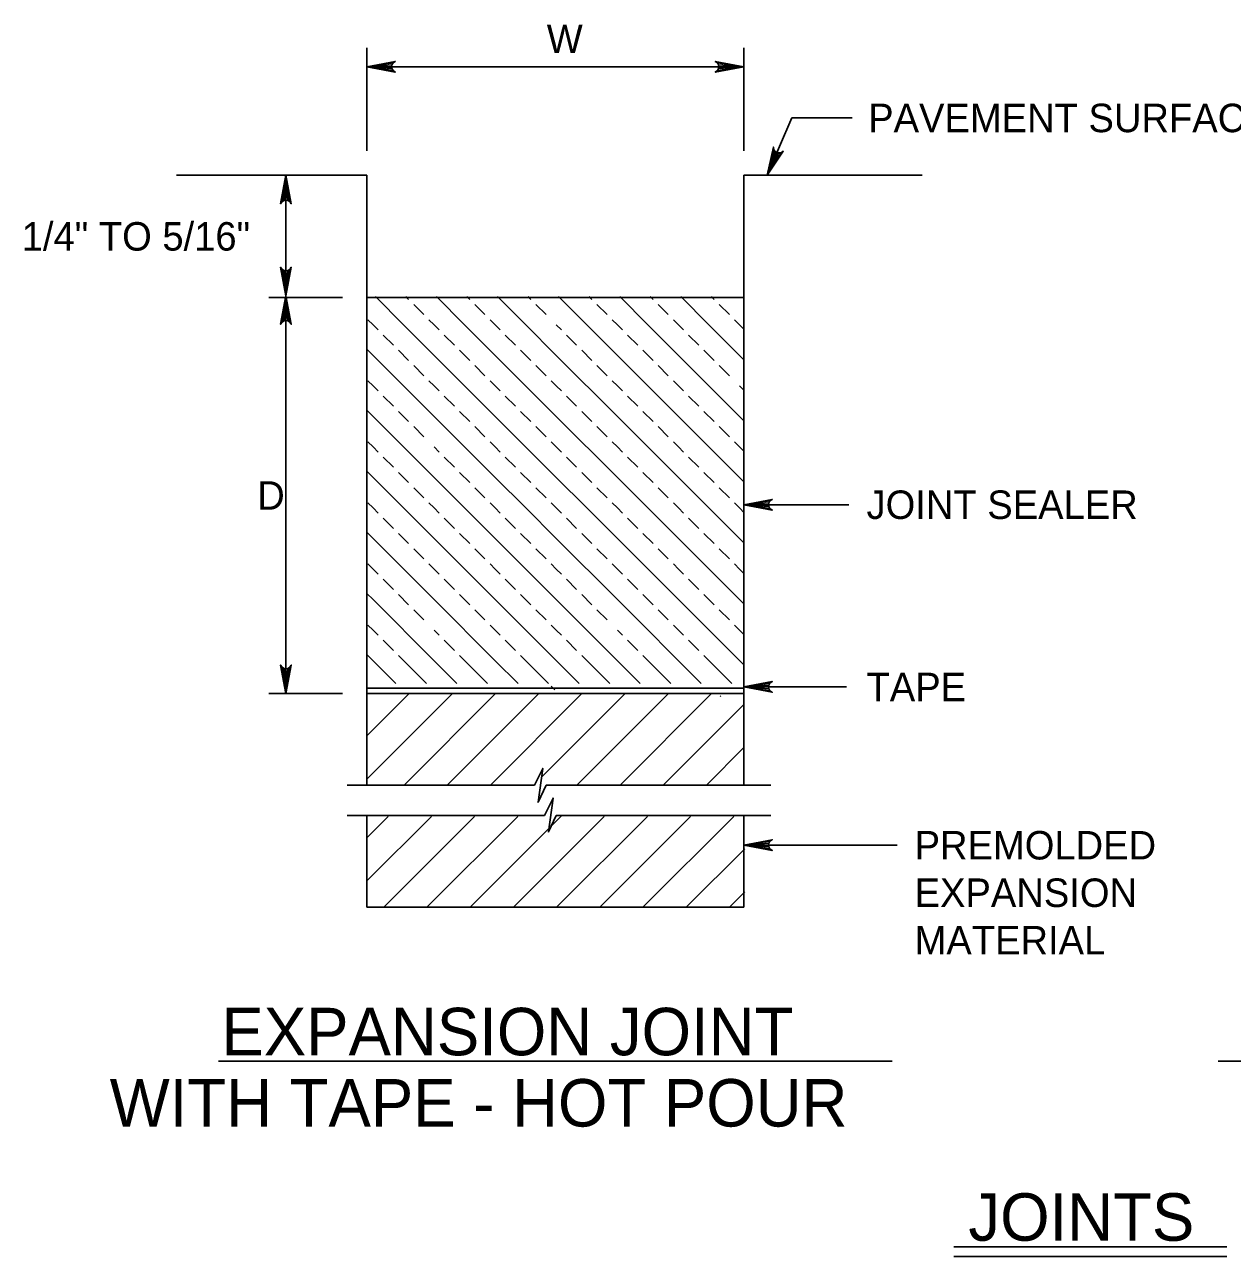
# Model space of a CAD drawing. Extents: x 1.68 to 8.95, y -3.21 to 6.76.
# Drawn here: x 3.018 to 5.56, y 4.163 to 6.756 of the extents above; entities that cross this region are included whole.
import ezdxf

# ---------------------------------------------------------------- set-up
doc = ezdxf.new("R2010")
doc.units = 0
for name, color, linetype in [('DETL-DIMS', 7, 'Continuous'), ('DETL-LINE', 7, 'Continuous'), ('DETL-NOTE', 7, 'Continuous'), ('DETL-PATT', 7, 'Continuous'), ('DETL-TITL', 7, 'Continuous')]:
    doc.layers.add(name, color=color, linetype=linetype)

msp = doc.modelspace()

# ---------------------------------------------------------------- linework, layer by layer
at = {"layer": 'DETL-DIMS'}
for p, q in [((3.7384, 6.7077), (3.7384, 6.4907)), ((4.5316, 6.7077), (4.5316, 6.4907)), ((3.7384, 6.6679), (4.5316, 6.6679)), ((4.5807, 6.4393), (4.633, 6.56)), ((4.7598, 6.56), (4.633, 6.56)), ((3.5682, 6.1821), (3.5682, 6.4393)), ((3.5323, 6.1821), (3.6869, 6.1821)), ((3.5682, 6.1821), (3.5682, 5.3482)), ((4.5316, 5.7457), (4.7529, 5.7457)), ((3.5323, 5.3482), (3.6869, 5.3482)), ((4.5316, 5.362), (4.7483, 5.362)), ((4.5316, 5.0292), (4.8547, 5.0292))]:
    msp.add_line(p, q, dxfattribs=at)
for points in [[(3.7384, 6.6679), (3.7983, 6.6791), (3.7937, 6.6759), (3.7913, 6.6719), (3.7906, 6.6679), (3.7913, 6.6639), (3.7937, 6.6598), (3.7983, 6.6566), (3.7384, 6.6679), (3.7937, 6.6598), (3.7913, 6.6639), (3.7384, 6.6679), (3.7906, 6.6679), (3.7913, 6.6719), (3.7384, 6.6679), (3.7937, 6.6759)], [(3.7384, 6.6679), (3.7983, 6.6791), (3.7937, 6.6759), (3.7913, 6.6719), (3.7906, 6.6679), (3.7913, 6.6639), (3.7937, 6.6598), (3.7983, 6.6566), (3.7384, 6.6679), (3.7937, 6.6598), (3.7913, 6.6639), (3.7384, 6.6679), (3.7906, 6.6679), (3.7913, 6.6719), (3.7384, 6.6679), (3.7937, 6.6759)], [(4.5316, 6.6679), (4.4717, 6.6566), (4.4763, 6.6598), (4.4787, 6.6639), (4.4794, 6.6679), (4.4787, 6.6719), (4.4763, 6.6759), (4.4717, 6.6791), (4.5316, 6.6679), (4.4763, 6.6759), (4.4787, 6.6719), (4.5316, 6.6679), (4.4794, 6.6679), (4.4787, 6.6639), (4.5316, 6.6679), (4.4763, 6.6598)], [(4.5807, 6.4393), (4.5942, 6.4987), (4.5953, 6.4932), (4.5981, 6.4894), (4.6015, 6.4872), (4.6055, 6.4862), (4.6101, 6.4868), (4.6149, 6.4898), (4.5807, 6.4393), (4.6101, 6.4868), (4.6055, 6.4862), (4.5807, 6.4393), (4.6015, 6.4872), (4.5981, 6.4894), (4.5807, 6.4393), (4.5953, 6.4932)], [(3.5682, 6.4393), (3.5794, 6.3794), (3.5762, 6.384), (3.5722, 6.3864), (3.5682, 6.387), (3.5641, 6.3864), (3.5601, 6.384), (3.5569, 6.3794), (3.5682, 6.4393), (3.5601, 6.384), (3.5641, 6.3864), (3.5682, 6.4393), (3.5682, 6.387), (3.5722, 6.3864), (3.5682, 6.4393), (3.5762, 6.384)], [(3.5682, 6.4393), (3.5794, 6.3794), (3.5762, 6.384), (3.5722, 6.3864), (3.5682, 6.387), (3.5641, 6.3864), (3.5601, 6.384), (3.5569, 6.3794), (3.5682, 6.4393), (3.5601, 6.384), (3.5641, 6.3864), (3.5682, 6.4393), (3.5682, 6.387), (3.5722, 6.3864), (3.5682, 6.4393), (3.5762, 6.384)], [(3.5682, 6.1856), (3.5794, 6.2456), (3.5762, 6.2409), (3.5722, 6.2386), (3.5682, 6.2379), (3.5641, 6.2386), (3.5601, 6.2409), (3.5569, 6.2456), (3.5682, 6.1856), (3.5601, 6.2409), (3.5641, 6.2386), (3.5682, 6.1856), (3.5682, 6.2379), (3.5722, 6.2386), (3.5682, 6.1856), (3.5762, 6.2409)], [(3.5682, 6.1856), (3.5794, 6.1257), (3.5762, 6.1303), (3.5722, 6.1327), (3.5682, 6.1334), (3.5641, 6.1327), (3.5601, 6.1303), (3.5569, 6.1257), (3.5682, 6.1856), (3.5601, 6.1303), (3.5641, 6.1327), (3.5682, 6.1856), (3.5682, 6.1334), (3.5722, 6.1327), (3.5682, 6.1856), (3.5762, 6.1303)], [(4.5316, 5.7457), (4.5916, 5.7569), (4.5869, 5.7537), (4.5846, 5.7497), (4.5839, 5.7457), (4.5846, 5.7417), (4.5869, 5.7376), (4.5916, 5.7344), (4.5316, 5.7457), (4.5869, 5.7376), (4.5846, 5.7417), (4.5316, 5.7457), (4.5839, 5.7457), (4.5846, 5.7497), (4.5316, 5.7457), (4.5869, 5.7537)], [(4.5316, 5.7457), (4.5916, 5.7569), (4.5869, 5.7537), (4.5846, 5.7497), (4.5839, 5.7457), (4.5846, 5.7417), (4.5869, 5.7376), (4.5916, 5.7344), (4.5316, 5.7457), (4.5869, 5.7376), (4.5846, 5.7417), (4.5316, 5.7457), (4.5839, 5.7457), (4.5846, 5.7497), (4.5316, 5.7457), (4.5869, 5.7537)], [(3.5682, 5.3482), (3.5569, 5.4082), (3.5601, 5.4035), (3.5641, 5.4012), (3.5682, 5.4005), (3.5722, 5.4012), (3.5762, 5.4035), (3.5794, 5.4082), (3.5682, 5.3482), (3.5762, 5.4035), (3.5722, 5.4012), (3.5682, 5.3482), (3.5682, 5.4005), (3.5641, 5.4012), (3.5682, 5.3482), (3.5601, 5.4035)], [(4.5316, 5.362), (4.5916, 5.3732), (4.5869, 5.37), (4.5846, 5.366), (4.5839, 5.362), (4.5846, 5.358), (4.5869, 5.354), (4.5916, 5.3508), (4.5316, 5.362), (4.5869, 5.354), (4.5846, 5.358), (4.5316, 5.362), (4.5839, 5.362), (4.5846, 5.366), (4.5316, 5.362), (4.5869, 5.37)], [(4.5316, 5.0292), (4.5916, 5.0404), (4.5869, 5.0372), (4.5846, 5.0332), (4.5839, 5.0292), (4.5846, 5.0252), (4.5869, 5.0212), (4.5916, 5.018), (4.5316, 5.0292), (4.5869, 5.0212), (4.5846, 5.0252), (4.5316, 5.0292), (4.5839, 5.0292), (4.5846, 5.0332), (4.5316, 5.0292), (4.5869, 5.0372)]]:
    msp.add_lwpolyline(points, dxfattribs=at)
at = {"layer": 'DETL-LINE'}
for p, q in [((3.3381, 6.4393), (3.7384, 6.4393)), ((3.7384, 5.1554), (3.7384, 6.4393)), ((4.5316, 6.4393), (4.5316, 5.1554)), ((4.5316, 6.4393), (4.9069, 6.4393)), ((3.7384, 6.1821), (4.5316, 6.1821)), ((3.8264, 6.178), (3.8207, 6.1838)), ((3.9549, 6.178), (3.9492, 6.1838)), ((4.0835, 6.178), (4.0778, 6.1838)), ((4.2121, 6.178), (4.2064, 6.1838)), ((4.3407, 6.178), (4.3349, 6.1838)), ((4.4692, 6.178), (4.4635, 6.1838)), ((3.7514, 6.1245), (3.7407, 6.1352)), ((4.5326, 6.1146), (4.5228, 6.1245)), ((3.7514, 6.0602), (3.7382, 6.0734)), ((4.5326, 6.0503), (4.5228, 6.0602)), ((4.5326, 5.9861), (4.5228, 5.9959)), ((4.5326, 5.9218), (4.5228, 5.9316)), ((3.7514, 5.8673), (3.7407, 5.878)), ((4.5326, 5.8575), (4.5228, 5.8673)), ((3.7514, 5.803), (3.7382, 5.8162)), ((4.5326, 5.7932), (4.5228, 5.803)), ((4.5326, 5.7289), (4.5228, 5.7388)), ((3.7514, 5.6745), (3.7382, 5.6876)), ((4.5326, 5.6646), (4.5228, 5.6745)), ((4.5326, 5.6003), (4.5228, 5.6102)), ((3.7514, 5.5459), (3.7382, 5.5591)), ((4.5326, 5.5361), (4.5228, 5.5459)), ((4.5326, 5.4718), (4.5228, 5.4816)), ((3.7514, 5.4173), (3.7382, 5.4305)), ((4.5316, 5.3594), (3.7384, 5.3594)), ((4.5316, 5.3482), (3.7384, 5.3482)), ((4.1338, 5.3563), (4.1264, 5.3638)), ((4.4818, 5.3419), (4.4833, 5.3434)), ((4.0913, 5.1554), (3.697, 5.1554)), ((4.5888, 5.1554), (4.1161, 5.1554)), ((4.1122, 5.0911), (3.697, 5.0911)), ((3.7384, 4.8982), (3.7384, 5.0911)), ((4.5888, 5.0911), (4.137, 5.0911)), ((4.5316, 4.8982), (4.5316, 5.0911)), ((4.5316, 4.8982), (3.7384, 4.8982))]:
    msp.add_line(p, q, dxfattribs=at)
for points in [[(4.0913, 5.1554), (4.1085, 5.1906), (4.0988, 5.1192), (4.1161, 5.1554)], [(4.1122, 5.0911), (4.1303, 5.1281), (4.1206, 5.0567), (4.137, 5.0911)]]:
    msp.add_lwpolyline(points, dxfattribs=at)
at = {"layer": 'DETL-NOTE'}
for p, q in [((3.4259, 4.574), (4.8441, 4.574)), ((5.5303, 4.574), (7.257, 4.574)), ((4.9739, 4.1836), (5.5486, 4.1836)), ((4.9739, 4.1632), (5.5486, 4.1632))]:
    msp.add_line(p, q, dxfattribs=at)
at = {"layer": 'DETL-PATT'}
for p, q in [((3.8157, 6.1245), (3.7564, 6.1838)), ((3.9442, 6.1245), (3.8849, 6.1838)), ((4.0728, 6.1245), (4.0135, 6.1838)), ((4.2014, 6.1245), (4.1421, 6.1838)), ((4.3299, 6.1245), (4.2707, 6.1838)), ((4.4585, 6.1245), (4.3992, 6.1838)), ((3.8585, 6.1459), (3.8371, 6.1673)), ((3.9871, 6.1459), (3.9657, 6.1673)), ((4.1157, 6.1459), (4.0942, 6.1673)), ((4.2442, 6.1459), (4.2228, 6.1673)), ((4.3728, 6.1459), (4.3514, 6.1673)), ((4.5014, 6.1459), (4.4799, 6.1673)), ((3.7621, 6.1138), (3.7514, 6.1245)), ((3.8799, 6.0602), (3.8157, 6.1245)), ((3.8799, 6.1245), (3.8692, 6.1352)), ((3.8907, 6.1138), (3.8799, 6.1245)), ((4.0085, 6.0602), (3.9442, 6.1245)), ((4.0085, 6.1245), (3.9978, 6.1352)), ((4.0192, 6.1138), (4.0085, 6.1245)), ((4.1371, 6.0602), (4.0728, 6.1245)), ((4.1478, 6.1138), (4.1371, 6.1245)), ((4.2657, 6.0602), (4.2014, 6.1245)), ((4.2657, 6.1245), (4.2549, 6.1352)), ((4.2764, 6.1138), (4.2657, 6.1245)), ((4.3942, 6.0602), (4.3299, 6.1245)), ((4.3942, 6.1245), (4.3835, 6.1352)), ((4.4049, 6.1138), (4.3942, 6.1245)), ((4.5228, 6.0602), (4.4585, 6.1245)), ((4.5228, 6.1245), (4.5121, 6.1352)), ((3.7942, 6.0816), (3.7728, 6.103)), ((3.9228, 6.0816), (3.9014, 6.103)), ((4.0514, 6.0816), (4.0299, 6.103)), ((4.1799, 6.0816), (4.1585, 6.103)), ((4.3085, 6.0816), (4.2871, 6.103)), ((4.4371, 6.0816), (4.4157, 6.103)), ((3.8264, 6.0495), (3.8049, 6.0709)), ((3.9549, 6.0495), (3.9335, 6.0709)), ((4.0835, 6.0495), (4.0621, 6.0709)), ((4.2121, 6.0495), (4.1907, 6.0709)), ((4.3407, 6.0495), (4.3192, 6.0709)), ((4.4692, 6.0495), (4.4478, 6.0709)), ((3.8799, 5.9316), (3.7514, 6.0602)), ((4.0085, 5.9316), (3.8799, 6.0602)), ((4.1371, 5.9316), (4.0085, 6.0602)), ((4.2657, 5.9316), (4.1371, 6.0602)), ((4.3942, 5.9316), (4.2657, 6.0602)), ((4.5228, 5.9316), (4.3942, 6.0602)), ((3.8585, 6.0173), (3.8371, 6.0388)), ((3.9871, 6.0173), (3.9657, 6.0388)), ((4.1157, 6.0173), (4.0942, 6.0388)), ((4.2442, 6.0173), (4.2228, 6.0388)), ((4.3728, 6.0173), (4.3514, 6.0388)), ((4.5014, 6.0173), (4.4799, 6.0388)), ((3.7514, 5.9959), (3.7407, 6.0066)), ((3.7621, 5.9852), (3.7514, 5.9959)), ((3.8799, 5.9959), (3.8692, 6.0066)), ((3.8907, 5.9852), (3.8799, 5.9959)), ((4.0085, 5.9959), (3.9978, 6.0066)), ((4.0192, 5.9852), (4.0085, 5.9959)), ((4.1371, 5.9959), (4.1264, 6.0066)), ((4.1478, 5.9852), (4.1371, 5.9959)), ((4.2657, 5.9959), (4.2549, 6.0066)), ((4.2764, 5.9852), (4.2657, 5.9959)), ((4.3942, 5.9959), (4.3835, 6.0066)), ((4.4049, 5.9852), (4.3942, 5.9959)), ((3.7942, 5.953), (3.7728, 5.9745)), ((3.9228, 5.953), (3.9014, 5.9745)), ((4.0514, 5.953), (4.0299, 5.9745)), ((4.1799, 5.953), (4.1585, 5.9745)), ((4.3085, 5.953), (4.2871, 5.9745)), ((4.4371, 5.953), (4.4157, 5.9745)), ((3.7514, 5.9316), (3.7382, 5.9448)), ((3.8264, 5.9209), (3.8049, 5.9423)), ((3.9549, 5.9209), (3.9335, 5.9423)), ((4.0835, 5.9209), (4.0621, 5.9423)), ((4.2121, 5.9209), (4.1907, 5.9423)), ((4.3407, 5.9209), (4.3192, 5.9423)), ((4.4692, 5.9209), (4.4478, 5.9423)), ((3.8799, 5.803), (3.7514, 5.9316)), ((4.0085, 5.803), (3.8799, 5.9316)), ((4.1371, 5.803), (4.0085, 5.9316)), ((4.2657, 5.803), (4.1371, 5.9316)), ((4.3942, 5.803), (4.2657, 5.9316)), ((4.5228, 5.803), (4.3942, 5.9316)), ((3.8585, 5.8888), (3.8371, 5.9102)), ((3.9871, 5.8888), (3.9657, 5.9102)), ((4.1157, 5.8888), (4.0942, 5.9102)), ((4.2442, 5.8888), (4.2228, 5.9102)), ((4.3728, 5.8888), (4.3514, 5.9102)), ((4.5014, 5.8888), (4.4799, 5.9102)), ((3.7621, 5.8566), (3.7514, 5.8673)), ((3.8907, 5.8566), (3.8799, 5.8673)), ((4.0085, 5.8673), (3.9978, 5.878)), ((4.0192, 5.8566), (4.0085, 5.8673)), ((4.1371, 5.8673), (4.1264, 5.878)), ((4.1478, 5.8566), (4.1371, 5.8673)), ((4.2657, 5.8673), (4.2549, 5.878)), ((4.2764, 5.8566), (4.2657, 5.8673)), ((4.3942, 5.8673), (4.3835, 5.878)), ((4.4049, 5.8566), (4.3942, 5.8673)), ((4.5228, 5.8673), (4.5121, 5.878)), ((3.7942, 5.8245), (3.7728, 5.8459)), ((3.9228, 5.8245), (3.9014, 5.8459)), ((4.0514, 5.8245), (4.0299, 5.8459)), ((4.1799, 5.8245), (4.1585, 5.8459)), ((4.3085, 5.8245), (4.2871, 5.8459)), ((4.4371, 5.8245), (4.4157, 5.8459)), ((3.8264, 5.7923), (3.8049, 5.8138)), ((3.9549, 5.7923), (3.9335, 5.8138)), ((4.0835, 5.7923), (4.0621, 5.8138)), ((4.2121, 5.7923), (4.1907, 5.8138)), ((4.3407, 5.7923), (4.3192, 5.8138)), ((4.4692, 5.7923), (4.4478, 5.8138)), ((3.8157, 5.7388), (3.7514, 5.803)), ((3.9442, 5.7388), (3.8799, 5.803)), ((4.0728, 5.7388), (4.0085, 5.803)), ((4.2014, 5.7388), (4.1371, 5.803)), ((4.3299, 5.7388), (4.2657, 5.803)), ((4.4585, 5.7388), (4.3942, 5.803)), ((3.8585, 5.7602), (3.8371, 5.7816)), ((3.9871, 5.7602), (3.9657, 5.7816)), ((4.1157, 5.7602), (4.0942, 5.7816)), ((4.2442, 5.7602), (4.2228, 5.7816)), ((4.3728, 5.7602), (4.3514, 5.7816)), ((4.5014, 5.7602), (4.4799, 5.7816)), ((3.7514, 5.7388), (3.7407, 5.7495)), ((3.7621, 5.728), (3.7514, 5.7388)), ((3.8799, 5.6745), (3.8157, 5.7388)), ((3.8799, 5.7388), (3.8692, 5.7495)), ((3.8907, 5.728), (3.8799, 5.7388)), ((4.0085, 5.6745), (3.9442, 5.7388)), ((4.0085, 5.7388), (3.9978, 5.7495)), ((4.0192, 5.728), (4.0085, 5.7388)), ((4.1371, 5.6745), (4.0728, 5.7388)), ((4.1371, 5.7388), (4.1264, 5.7495)), ((4.1478, 5.728), (4.1371, 5.7388)), ((4.2657, 5.6745), (4.2014, 5.7388)), ((4.2657, 5.7388), (4.2549, 5.7495)), ((4.2764, 5.728), (4.2657, 5.7388)), ((4.3942, 5.6745), (4.3299, 5.7388)), ((4.3942, 5.7388), (4.3835, 5.7495)), ((4.4049, 5.728), (4.3942, 5.7388)), ((4.5228, 5.6745), (4.4585, 5.7388)), ((4.5228, 5.7388), (4.5121, 5.7495)), ((3.7942, 5.6959), (3.7728, 5.7173)), ((3.9228, 5.6959), (3.9014, 5.7173)), ((4.0514, 5.6959), (4.0299, 5.7173)), ((4.1799, 5.6959), (4.1585, 5.7173)), ((4.3085, 5.6959), (4.2871, 5.7173)), ((4.4371, 5.6959), (4.4157, 5.7173)), ((3.8264, 5.6638), (3.8049, 5.6852)), ((3.9549, 5.6638), (3.9335, 5.6852)), ((4.0835, 5.6638), (4.0621, 5.6852)), ((4.2121, 5.6638), (4.1907, 5.6852)), ((4.3407, 5.6638), (4.3192, 5.6852)), ((4.4692, 5.6638), (4.4478, 5.6852)), ((3.8799, 5.5459), (3.7514, 5.6745)), ((4.0085, 5.5459), (3.8799, 5.6745)), ((4.1371, 5.5459), (4.0085, 5.6745)), ((4.2657, 5.5459), (4.1371, 5.6745)), ((4.3942, 5.5459), (4.2657, 5.6745)), ((4.5228, 5.5459), (4.3942, 5.6745)), ((3.8585, 5.6316), (3.8371, 5.653)), ((3.9871, 5.6316), (3.9657, 5.653)), ((4.1157, 5.6316), (4.0942, 5.653)), ((4.2442, 5.6316), (4.2228, 5.653)), ((4.3728, 5.6316), (4.3514, 5.653)), ((4.5014, 5.6316), (4.4799, 5.653)), ((3.7514, 5.6102), (3.7407, 5.6209)), ((3.7621, 5.5995), (3.7514, 5.6102)), ((3.8799, 5.6102), (3.8692, 5.6209)), ((3.8907, 5.5995), (3.8799, 5.6102)), ((4.0085, 5.6102), (3.9978, 5.6209)), ((4.0192, 5.5995), (4.0085, 5.6102)), ((4.1371, 5.6102), (4.1264, 5.6209)), ((4.1478, 5.5995), (4.1371, 5.6102)), ((4.2657, 5.6102), (4.2549, 5.6209)), ((4.2764, 5.5995), (4.2657, 5.6102)), ((4.3942, 5.6102), (4.3835, 5.6209)), ((4.4049, 5.5995), (4.3942, 5.6102)), ((4.5228, 5.6102), (4.5121, 5.6209)), ((3.7942, 5.5673), (3.7728, 5.5888)), ((3.9228, 5.5673), (3.9014, 5.5888)), ((4.0514, 5.5673), (4.0299, 5.5888)), ((4.1799, 5.5673), (4.1585, 5.5888)), ((4.3085, 5.5673), (4.2871, 5.5888)), ((4.4371, 5.5673), (4.4157, 5.5888)), ((3.8264, 5.5352), (3.8049, 5.5566)), ((3.9549, 5.5352), (3.9335, 5.5566)), ((4.0835, 5.5352), (4.0621, 5.5566)), ((4.2121, 5.5352), (4.1907, 5.5566)), ((4.3407, 5.5352), (4.3192, 5.5566)), ((4.4692, 5.5352), (4.4478, 5.5566)), ((3.8799, 5.4173), (3.7514, 5.5459)), ((3.8585, 5.503), (3.8371, 5.5245)), ((4.0085, 5.4173), (3.8799, 5.5459)), ((3.9871, 5.503), (3.9657, 5.5245)), ((4.1853, 5.3691), (4.0085, 5.5459)), ((4.1157, 5.503), (4.0942, 5.5245)), ((4.3139, 5.3691), (4.1371, 5.5459)), ((4.2442, 5.503), (4.2228, 5.5245)), ((4.4424, 5.3691), (4.2657, 5.5459)), ((4.3728, 5.503), (4.3514, 5.5245)), ((4.5316, 5.4085), (4.3942, 5.5459)), ((4.5014, 5.503), (4.4799, 5.5245)), ((3.7514, 5.4816), (3.7407, 5.4923)), ((3.7621, 5.4709), (3.7514, 5.4816)), ((3.8907, 5.4709), (3.8799, 5.4816)), ((4.0085, 5.4816), (3.9978, 5.4923)), ((4.0192, 5.4709), (4.0085, 5.4816)), ((4.1371, 5.4816), (4.1264, 5.4923)), ((4.1478, 5.4709), (4.1371, 5.4816)), ((4.2764, 5.4709), (4.2657, 5.4816)), ((4.3942, 5.4816), (4.3835, 5.4923)), ((4.4049, 5.4709), (4.3942, 5.4816)), ((4.5228, 5.4816), (4.5121, 5.4923)), ((3.7942, 5.4388), (3.7728, 5.4602)), ((3.9228, 5.4388), (3.9014, 5.4602)), ((4.0514, 5.4388), (4.0299, 5.4602)), ((4.1799, 5.4388), (4.1585, 5.4602)), ((4.3085, 5.4388), (4.2871, 5.4602)), ((4.4371, 5.4388), (4.4157, 5.4602)), ((3.8639, 5.3691), (3.8049, 5.428)), ((3.9924, 5.3691), (3.9335, 5.428)), ((4.121, 5.3691), (4.0621, 5.428)), ((4.2496, 5.3691), (4.1907, 5.428)), ((4.3781, 5.3691), (4.3192, 5.428)), ((4.5067, 5.3691), (4.4478, 5.428)), ((3.7996, 5.3691), (3.7514, 5.4173)), ((3.9281, 5.3691), (3.8799, 5.4173)), ((4.0567, 5.3691), (4.0085, 5.4173)), ((3.7377, 5.2582), (3.8262, 5.3467)), ((3.7377, 5.1673), (3.9171, 5.3467)), ((3.8176, 5.1563), (4.008, 5.3467)), ((3.9085, 5.1563), (4.0989, 5.3467)), ((3.9994, 5.1563), (4.1898, 5.3467)), ((4.106, 5.172), (4.2808, 5.3467)), ((4.1813, 5.1563), (4.3717, 5.3467)), ((4.2722, 5.1563), (4.4626, 5.3467)), ((4.3631, 5.1563), (4.5322, 5.3254)), ((4.454, 5.1563), (4.5322, 5.2345)), ((3.7377, 5.0437), (3.7834, 5.0895)), ((3.7377, 4.9528), (3.8744, 5.0895)), ((3.774, 4.8982), (3.9653, 5.0895)), ((3.865, 4.8982), (4.0562, 5.0895)), ((4.0468, 4.8982), (4.238, 5.0895)), ((4.1263, 5.0687), (4.1487, 5.0911)), ((4.1377, 4.8982), (4.3289, 5.0895)), ((4.2286, 4.8982), (4.4198, 5.0895)), ((4.3195, 4.8982), (4.5108, 5.0895)), ((3.9559, 4.8982), (4.1216, 5.064)), ((4.4104, 4.8982), (4.5337, 5.0215)), ((4.5014, 4.8982), (4.5337, 4.9305))]:
    msp.add_line(p, q, dxfattribs=at)

# ---------------------------------------------------------------- texts
at = {"layer": 'DETL-NOTE'}
for s, p in [('W', (4.1171, 6.6964)), ('PAVEMENT SURFACE', (4.7936, 6.53)), ('1/4" TO 5/16"', (3.0121, 6.2807)), ('D', (3.5077, 5.7352)), ('JOINT SEALER', (4.7902, 5.7157)), ('TAPE', (4.7901, 5.332)), ('PREMOLDED ', (4.8913, 4.9988)), ('EXPANSION', (4.8913, 4.8988)), ('MATERIAL', (4.8913, 4.7988))]:
    msp.add_text(s, height=0.06, dxfattribs=at).set_placement(p)
at = {"layer": 'DETL-TITL'}
for s, p in [('EXPANSION JOINT', (3.4324, 4.5865)), ('WITH TAPE - HOT POUR', (3.1973, 4.4365)), ('JOINTS', (5.0045, 4.1961))]:
    msp.add_text(s, height=0.1, dxfattribs=at).set_placement(p)

doc.saveas('drawing.dxf')
